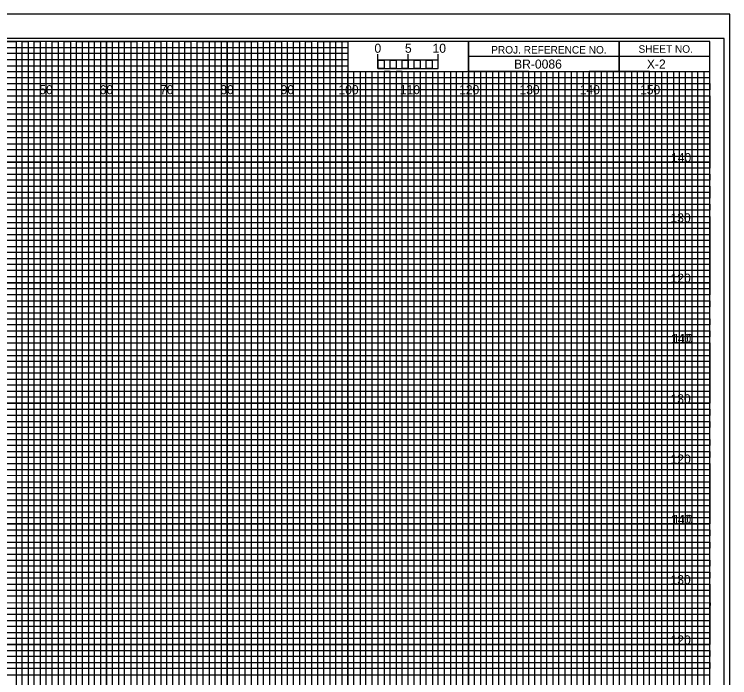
# Model space of a CAD drawing. Extents: x -13 to 371, y -5 to 215.
# Drawn here: x 204.7 to 323.3, y 104.5 to 214.5 of the extents above; entities that cross this region are included whole.
import ezdxf

# ---------------------------------------------------------------- set-up
doc = ezdxf.new("R2010")
doc.units = 0
for name, color, linetype in [('Exist CMT Pavement', 7, 'Continuous'), ('Exist Cross Section Cell', 7, 'Continuous'), ('Exist XS Center Line Elevation Label', 7, 'Continuous'), ('Exist XS Ground Line', 7, 'Continuous'), ('Prop CMT Pvmt Course 1 Wedge', 7, 'Continuous'), ('Prop CMT Pvmt Course 2', 7, 'Continuous'), ('Prop CMT Pvmt Course 3', 7, 'Continuous'), ('Prop CMT Pvmt Course 3 Wedge', 7, 'Continuous'), ('Prop CMT Pvmt Wedge Surface 1', 7, 'Continuous'), ('Prop CMT Shld Paved Course 1', 7, 'Continuous'), ('Prop CMT Shld Paved Course 2', 7, 'Continuous'), ('Prop CMT Shld Paved Course 3', 7, 'Continuous'), ('Prop CMT Slope Grass', 7, 'Continuous'), ('Prop CMT Subgrade Earthwork', 7, 'Continuous'), ('Scratch_Level_0', 7, 'Continuous')]:
    doc.layers.add(name, color=color, linetype=linetype)

msp = doc.modelspace()

# ---------------------------------------------------------------- linework, layer by layer
at = {"layer": 'Exist XS Center Line Elevation Label'}
for points in [[(195, 210), (205, 210), (205, 0)], [(215, 0), (215, 210), (225, 210), (225, 0)], [(235, 0), (235, 210), (245, 210), (245, 0)], [(255, 0), (255, 210), (259.93, 210), (260, 210), (260, 205), (264.99, 205), (264.99, 0)], [(0, 205), (275, 205)], [(275, 0), (275, 205), (285, 205), (285, 0)], [(295, 0), (295, 205), (305, 205), (305, 0)], [(315, 0), (315, 205)], [(0, 185), (320, 185), (320, 195), (0, 195)], [(0, 165), (320, 165), (320, 175), (0, 175)], [(0, 145), (320, 145), (320, 155), (0, 155)], [(0, 125), (320, 125), (320, 135), (0, 135)], [(0, 105), (320, 105), (320, 115), (0, 115)]]:
    msp.add_lwpolyline(points, dxfattribs=at)
at = {"layer": 'Exist XS Ground Line'}
for p, q in [((210, 210), (200, 210)), ((210, 0), (210, 210)), ((230, 210), (220, 210)), ((220, 210), (220, 0)), ((230, 0), (230, 210)), ((250, 210), (240, 210)), ((240, 210), (240, 0)), ((250, 0), (250, 210)), ((260, 210), (260, 0)), ((270, 0), (270, 205)), ((290, 205), (280, 205)), ((280, 205), (280, 0)), ((290, 0), (290, 205)), ((310, 205), (300, 205)), ((300, 205), (300, 0)), ((310, 0), (310, 205))]:
    msp.add_line(p, q, dxfattribs=at)
for points in [[(0, 200), (320, 200), (320, 190), (0, 190)], [(0, 180), (320, 180), (320, 170), (0, 170)], [(0, 160), (320, 160), (320, 150), (0, 150)], [(0, 140), (320, 140), (320, 130), (0, 130)], [(0, 120), (320, 120), (320, 110), (0, 110)]]:
    msp.add_lwpolyline(points, dxfattribs=at)
at = {"layer": 'Prop CMT Pvmt Course 2'}
for p, q in [((210, 0), (210, 210)), ((220, 0), (220, 210)), ((230, 0), (230, 210)), ((240, 0), (240, 210)), ((250, 0), (250, 210)), ((260, 0), (260, 204.69)), ((270, 0), (270, 204.69)), ((280, 0), (280, 204.69)), ((290, 0), (290, 204.69)), ((300, 0), (300, 204.69)), ((310, 0), (310, 204.69)), ((0, 200), (320, 200)), ((0, 190), (320, 190)), ((0, 180), (320, 180)), ((0, 170), (320, 170)), ((0, 160), (320, 160)), ((0, 150), (320, 150)), ((0, 140), (320, 140)), ((0, 130), (320, 130)), ((0, 120), (320, 120)), ((0, 110), (320, 110))]:
    msp.add_line(p, q, dxfattribs=at)
at = {"layer": 'Prop CMT Pvmt Course 3'}
msp.add_line((323.3, 214.5), (-13.4, 214.5), dxfattribs=at)
at = {"layer": 'Prop CMT Shld Paved Course 1'}
for p, q in [((265, 205.49), (265, 207.9)), ((265, 206.9), (265, 207.9)), ((270, 205.49), (270, 207.9)), ((275, 205.49), (275, 207.9)), ((275, 206.9), (275, 207.9))]:
    msp.add_line(p, q, dxfattribs=at)
for points in [[(275, 206.9), (265, 206.9), (265, 205.49), (275, 205.49)], [(265, 206.9), (266, 206.9), (266, 205.49), (265, 205.49)], [(267, 206.9), (268, 206.9), (268, 205.49), (267, 205.49)], [(269, 206.9), (270, 206.9), (270, 205.49), (269, 205.49)], [(271, 206.9), (272, 206.9), (272, 205.49), (271, 205.49)], [(273, 206.9), (274, 206.9), (274, 205.49), (273, 205.49)]]:
    msp.add_lwpolyline(points, close=True, dxfattribs=at)
at = {"layer": 'Prop CMT Shld Paved Course 2'}
msp.add_lwpolyline([(-13.4, -4.5), (323.3, -4.5), (323.3, 214.5), (-13.4, 214.5)], close=True, dxfattribs=at)
at = {"layer": 'Prop CMT Shld Paved Course 3'}
msp.add_lwpolyline([(-10.8, -0.5), (322.4, -0.5), (322.4, 210.5), (-10.8, 210.5)], close=True, dxfattribs=at)
at = {"layer": 'Prop CMT Slope Grass'}
for p, q in [((267, 205), (266.01, 205)), ((266.01, 205), (266.01, 0)), ((267, 0), (267, 205)), ((269, 205), (268, 205)), ((268, 205), (268, 0)), ((269, 0), (269, 205))]:
    msp.add_line(p, q, dxfattribs=at)
for points in [[(205, 0), (206, 0), (206, 210), (207, 210), (207, 0)], [(207, 0), (208, 0), (208, 210), (209, 210), (209, 0)], [(210, 0), (211, 0), (211, 210), (212, 210), (212, 0)], [(212, 0), (213, 0), (213, 210), (214, 210), (214, 0)], [(215, 0), (216, 0), (216, 210), (217, 210), (217, 0)], [(217, 0), (218, 0), (218, 210), (219, 210), (219, 0)], [(220, 0), (221, 0), (221, 210), (222, 210), (222, 0)], [(222, 0), (223, 0), (223, 210), (224, 210), (224, 0)], [(225, 0), (226, 0), (226, 210), (227, 210), (227, 0)], [(227, 0), (228, 0), (228, 210), (229, 210), (229, 0)], [(230, 0), (231, 0), (231, 210), (232, 210), (232, 0)], [(232, 0), (233, 0), (233, 210), (234, 210), (234, 0)], [(235, 0), (236, 0), (236, 210), (237, 210), (237, 0)], [(237, 0), (238, 0), (238, 210), (239, 210), (239, 0)], [(240, 0), (241, 0), (241, 210), (242, 210), (242, 0)], [(242, 0), (243, 0), (243, 210), (244, 210), (244, 0)], [(245, 0), (246, 0), (246, 210), (247, 210), (247, 0)], [(247, 0), (248, 0), (248, 210), (249, 210), (249, 0)], [(250, 0), (251, 0), (251, 210), (252, 210), (252, 0)], [(252, 0), (253, 0), (253, 210), (254, 210), (254, 0)], [(255, 0), (256, 0), (256, 210), (257, 210), (257, 0)], [(257, 0), (258, 0), (258, 210), (259, 210), (259, 0)], [(260, 0), (261, 0), (261, 205), (262.02, 205), (262.02, 0)], [(262, 0), (263, 0), (263, 205), (263.99, 205), (263.99, 0)], [(270, 0), (270.98, 0), (270.98, 205), (272, 205), (272, 0)], [(272, 0), (273, 0), (273, 205), (274.05, 205), (274.05, 0)], [(275, 0), (276, 0), (276, 205), (277, 205), (277, 0)], [(277, 0), (278, 0), (278, 205), (279, 205), (279, 0)], [(280, 0), (281, 0), (281, 205), (282, 205), (282, 0)], [(282, 0), (283, 0), (283, 205), (284, 205), (284, 0)], [(285, 0), (286, 0), (286, 205), (287, 205), (287, 0)], [(287, 0), (288, 0), (288, 205), (289, 205), (289, 0)], [(290, 0), (291, 0), (291, 205), (292, 205), (292, 0)], [(292, 0), (293, 0), (293, 205), (294, 205), (294, 0)], [(295, 0), (296, 0), (296, 205), (297, 205), (297, 0)], [(297, 0), (298, 0), (298, 205), (299, 205), (299, 0)], [(300, 0), (301, 0), (301, 205), (302, 205), (302, 0)], [(302, 0), (303, 0), (303, 205), (304, 205), (304, 0)], [(305, 0), (306, 0), (306, 205), (307, 205), (307, 0)], [(307, 0), (308, 0), (308, 205), (309, 205), (309, 0)], [(310, 0), (311, 0), (311, 205), (312, 205), (312, 0)], [(312, 0), (313, 0), (313, 205), (314, 205), (314, 0)], [(315, 0), (316, 0), (316, 205), (317, 205), (317, 0)], [(317, 0), (318, 0), (318, 205), (319, 205), (319, 0)]]:
    msp.add_lwpolyline(points, dxfattribs=at)
at = {"layer": 'Prop CMT Subgrade Earthwork'}
for p, q in [((305, 210), (305, 205)), ((305, 205), (305, 210)), ((280, 207.5), (280, 205)), ((320, 207.49), (280, 207.49)), ((280, 205), (320, 205))]:
    msp.add_line(p, q, dxfattribs=at)
for points in [[(320, 210), (0, 210), (0, 0), (320, 0)], [(280, 210), (260, 210), (260, 205.03), (280, 205.03)], [(320, 210), (280, 210), (280, 205), (320, 205)]]:
    msp.add_lwpolyline(points, close=True, dxfattribs=at)
at = {"layer": 'Scratch_Level_0'}
for p, q in [((0, 209), (260, 209)), ((260, 209), (260, 207.98)), ((260, 207.98), (0, 207.98)), ((0, 207), (260, 207)), ((260, 207), (260, 205.89)), ((260, 205.89), (0, 205.89)), ((0, 204), (320, 204))]:
    msp.add_line(p, q, dxfattribs=at)
for points in [[(0, 203), (270, 203), (320, 203), (320, 202), (0, 202)], [(0, 201), (320, 201), (320, 199), (0, 199)], [(0, 198), (320, 198), (320, 197), (0, 196.98)], [(0, 196), (320, 196), (320, 194), (0, 194)], [(0, 193), (320, 193), (320, 192), (0, 192)], [(0, 191), (320, 191), (320, 189), (0, 189)], [(0, 188), (320, 188), (320, 187), (0, 187)], [(0, 186), (320, 186), (320, 184), (0, 184)], [(0, 183), (320, 183), (320, 182), (0, 182)], [(0, 181), (320, 181), (320, 179), (0, 179)], [(0, 178), (320, 178), (320, 177), (0, 177)], [(0, 176), (320, 176), (320, 173.95), (320, 173), (320, 172), (0, 172)], [(0, 174), (320, 174), (320, 173), (0, 173)], [(0, 171), (320, 171), (320, 169), (0, 169.03)], [(0, 169.03), (320, 169), (320, 168), (0, 168)], [(0, 167), (320, 167), (320, 166), (0, 166)], [(0, 164), (320, 164), (320, 163), (0, 163)], [(0, 162), (320, 162), (320, 161), (0, 161)], [(-0.07, 158.89), (320, 158.89), (320, 157.88), (-0.07, 157.88)], [(0, 157), (320, 157), (320, 156), (0, 156)], [(0, 154), (320, 154), (320, 153), (0, 153)], [(0, 152), (320, 152), (320, 151), (0, 151)], [(0, 149), (320, 149), (320, 148), (0, 148)], [(0, 147), (320, 147), (320, 146), (0, 146)], [(0, 144), (320, 144), (320, 143), (0, 143)], [(0, 142), (320, 142), (320, 141), (0, 141)], [(0, 139), (320, 139), (319.99, 137.98), (0, 138)], [(0, 137), (320, 137), (320, 136), (0, 136)], [(0, 134), (320, 134), (320, 133), (0, 133)], [(0, 132), (320, 132), (320, 131), (0, 131)], [(0, 129), (320, 129), (320, 128), (0, 128)], [(0, 127), (320, 127), (320, 126), (0, 126)], [(0, 124), (320, 124), (320, 123), (0, 123)], [(0, 122), (320, 122), (320, 121), (0, 121)], [(0, 119), (320, 119), (320, 118), (0, 118)], [(0, 116.99), (320.07, 116.91), (320, 116), (0, 116)], [(0, 114), (320, 114), (320, 113), (0, 113)], [(0, 112), (320, 112), (320, 111), (0, 111)], [(0, 109), (320, 109), (320, 108), (0, 108)], [(0, 107), (320, 107), (320, 106), (0, 106)]]:
    msp.add_lwpolyline(points, dxfattribs=at)

# ---------------------------------------------------------------- texts
at = {"layer": 'Exist CMT Pavement'}
msp.add_text('BR-0086', height=1.5, dxfattribs=at).set_placement((287.56, 205.5))
at = {"layer": 'Exist Cross Section Cell'}
for s, p in [('50', (208.86, 201.25)), ('60', (218.86, 201.25)), ('70', (228.86, 201.25)), ('80', (238.86, 201.25)), ('90', (248.86, 201.25)), ('100', (258.44, 201.25)), ('110', (268.62, 201.25)), ('120', (278.44, 201.25)), ('130', (288.44, 201.25)), ('140', (298.44, 201.25)), ('150', (308.44, 201.25))]:
    msp.add_text(s, height=1.5, dxfattribs=at).set_placement(p)
at = {"layer": 'Prop CMT Pvmt Course 1 Wedge'}
for s, p in [('140', (313.57, 190)), ('130', (313.49, 180)), ('120', (313.5, 170)), ('140', (313.57, 160)), ('110', (313.88, 160)), ('130', (313.49, 150)), ('120', (313.5, 140)), ('140', (313.57, 130)), ('110', (313.88, 130)), ('130', (313.49, 120)), ('120', (313.5, 110))]:
    msp.add_text(s, height=1.5, dxfattribs=at).set_placement(p)
at = {"layer": 'Prop CMT Pvmt Course 3 Wedge'}
msp.add_text('X-2', height=1.5, dxfattribs=at).set_placement((309.57, 205.5))
at = {"layer": 'Prop CMT Pvmt Wedge Surface 1'}
for s, p in [('5', (269.47, 208.12)), ('10', (274.04, 208.12))]:
    msp.add_text(s, height=1.5, dxfattribs=at).set_placement(p)
at = {"layer": 'Prop CMT Shld Paved Course 1'}
msp.add_text('0', height=1.5, dxfattribs=at).set_placement((264.41, 208.12))
at = {"layer": 'Prop CMT Subgrade Earthwork'}
for s, p in [('PROJ. REFERENCE NO.', (283.77, 207.99)), ('SHEET NO.', (308.19, 208.12))]:
    msp.add_text(s, height=1.25, dxfattribs=at).set_placement(p)

doc.saveas('drawing.dxf')
